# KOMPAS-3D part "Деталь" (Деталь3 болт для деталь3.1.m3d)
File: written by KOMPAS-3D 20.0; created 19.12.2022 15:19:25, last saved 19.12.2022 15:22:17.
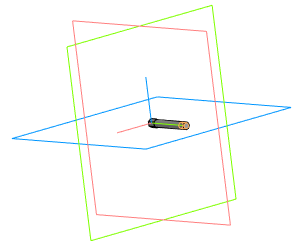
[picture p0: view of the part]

Document properties: Полное имя файла: C:\Users\Семья\Desktop\ДЕТАЛИ ДЛЯ СБОРЩИКА БОРЩЕВИКА\ДЕТАЛИ ДЛЯ ФИНАЛА\Деталь3 болт для деталь3.1.m3d

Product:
- Part/product: Деталь
    Масса: 0.000325912

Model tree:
1. Эскиз:1
2. Элемент выдавливания:1
     Расстояние 1 = 2
3. Эскиз:2  (with: Элемент выдавливания:1)
4. Элемент выдавливания:2
     Расстояние 1 = 11
5. Условное изображение резьбы:1  (with: Элемент выдавливания:2)  (labels: M2; cil0_24705-2004 coarse)
     Длина резьбы = 2; Шаг резьбы = 0.4; Номинальный диаметр резьбы = 2
6. Подгонка:1  (with: Элемент выдавливания:2)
